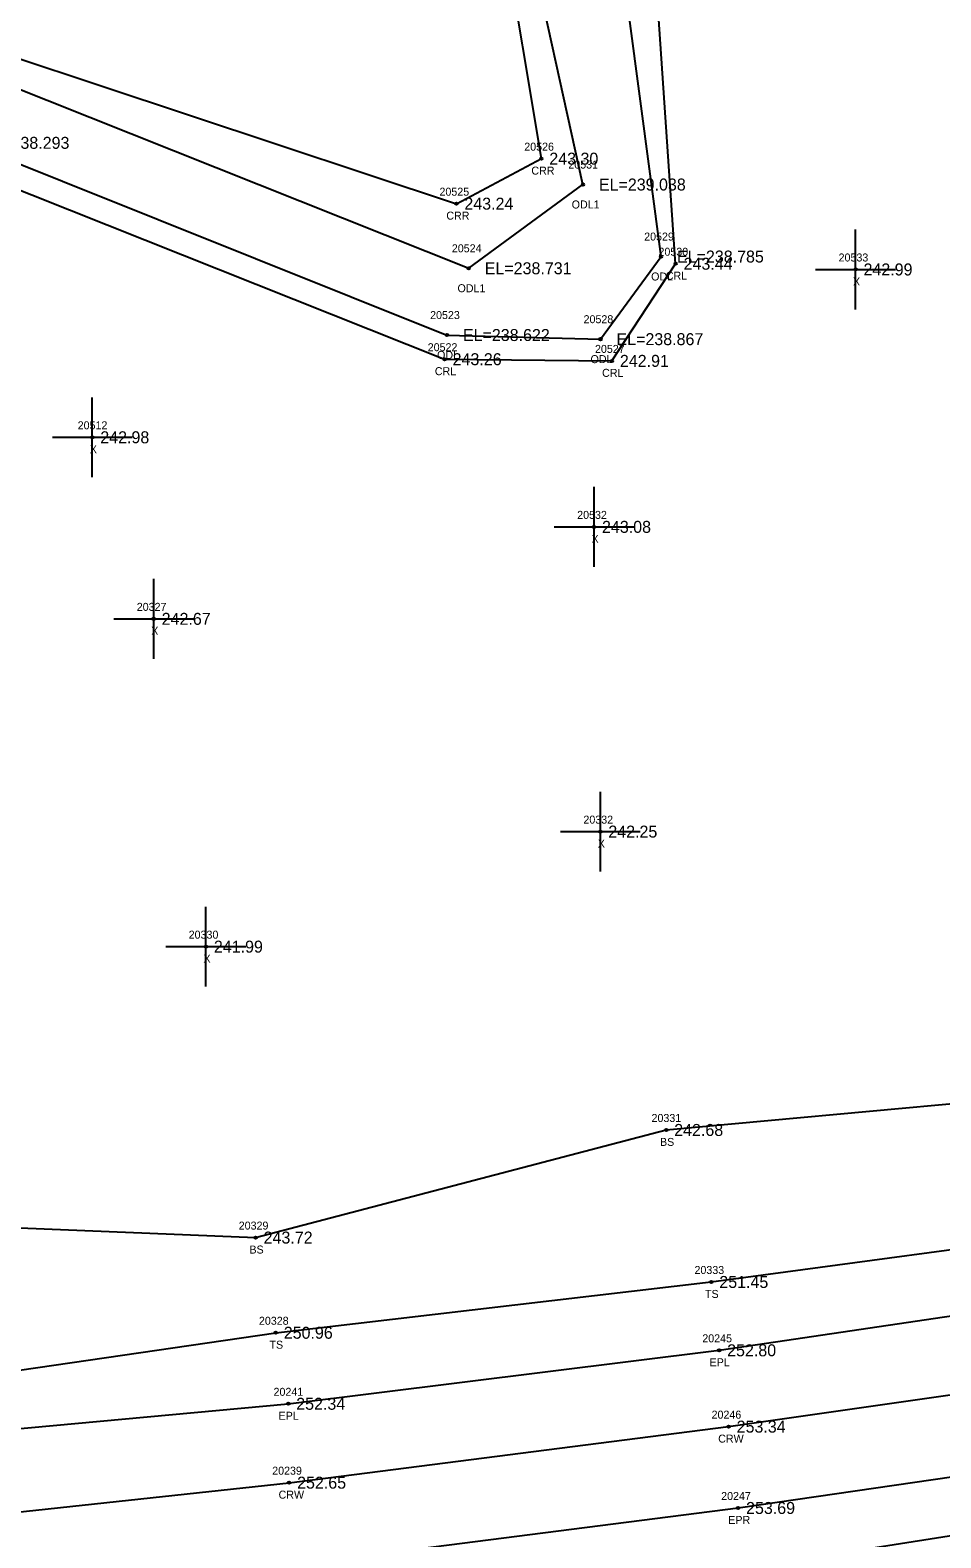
# Model space of a CAD drawing. Extents: x 2275563 to 2277161, y 1075719 to 1076412.
# Drawn here: x 2276399.9 to 2276514, y 1076072.5 to 1076261.3 of the extents above; entities that cross this region are included whole.
import ezdxf

# ---------------------------------------------------------------- set-up
doc = ezdxf.new("R2010")
doc.units = 0
for name, color, linetype in [('RD_DTM_BkLn1', 7, 'Continuous'), ('RD_DTM_BkLn2', 7, 'Continuous'), ('RD_DTM_BkLn_txCode', 7, 'Continuous'), ('RD_EX_H2O', 7, 'Continuous'), ('RD_EX_H2O_txCode', 7, 'Continuous'), ('RD_EX_Misc', 7, 'Continuous'), ('RD_EX_Misc_txCode', 7, 'Continuous'), ('RD_EX_Road', 7, 'Continuous'), ('RD_EX_Road_txCode', 7, 'Continuous'), ('RD_EX_TX_H2O_ELEV', 7, 'Continuous'), ('RD_EX_TX_Misc_ELEV', 7, 'Continuous'), ('RD_EX_TX_Road_ELEV', 7, 'Continuous'), ('RD_HC_Survey_ELEV', 7, 'Continuous'), ('RD_HC_Survey_txCode', 7, 'Continuous'), ('RD_SMD_Locator', 7, 'Continuous')]:
    doc.layers.add(name, color=color, linetype=linetype)

msp = doc.modelspace()

# ---------------------------------------------------------------- linework, layer by layer
at = {"layer": 'RD_DTM_BkLn1'}
msp.add_lwpolyline([(2276380.47, 1076073.8), (2276432.36, 1076079.4), (2276487.41, 1076086.42), (2276535.62, 1076093.32), (2276578.15, 1076099.97), (2276622.03, 1076107.93), (2276668.51, 1076117.27), (2276714.2, 1076127.81), (2276762.94, 1076140.11), (2276806.88, 1076151.96), (2276854.94, 1076166.29), (2276899.73, 1076180.7), (2276952.88, 1076198.57), (2277000.46, 1076214.72), (2277057.1, 1076234.01), (2277134.93, 1076261.07)], dxfattribs=at)
at = {"layer": 'RD_DTM_BkLn2'}
for points in [[(2276352.82, 1076100.61), (2276380.25, 1076112.06), (2276428.17, 1076110.1), (2276479.59, 1076123.58), (2276530.51, 1076128.25), (2276572.26, 1076136.92), (2276616.95, 1076145.31), (2276657.47, 1076152.34)], [(2276378.73, 1076086.44), (2276379.33, 1076090.71), (2276430.69, 1076098.18), (2276485.24, 1076104.54), (2276534.86, 1076111.23), (2276576.67, 1076117.6), (2276619.01, 1076127.99), (2276664.32, 1076137.81), (2276675.37, 1076140.15)], [(2276381.23, 1076060.52), (2276384.72, 1076057.35), (2276432.14, 1076059.24), (2276489.29, 1076068.7), (2276538.36, 1076076.43), (2276580.68, 1076083.56), (2276626.16, 1076090.05), (2276659.02, 1076095.85)]]:
    msp.add_lwpolyline(points, dxfattribs=at)
at = {"layer": 'RD_EX_H2O'}
for points in [[(2276337.52, 1076082.32), (2276338.14, 1076090.91), (2276325.39, 1076121.38), (2276301.23, 1076176.38), (2276301.47, 1076212.03), (2276303.94, 1076212.33), (2276322.96, 1076208.7), (2276333.72, 1076197.42), (2276353.59, 1076194.54), (2276358.22, 1076208.33), (2276360.94, 1076233.4), (2276370.36, 1076250.64), (2276386.18, 1076258.85), (2276454.86, 1076231.51), (2276469.16, 1076242), (2276461.94, 1076274.88), (2276441.6, 1076298.83), (2276443.32, 1076327.87), (2276470.76, 1076362.4), (2276481.62, 1076405.55)], [(2276371.99, 1076084.86), (2276359.12, 1076090.36), (2276349.87, 1076095.47), (2276335.93, 1076128.95), (2276310.08, 1076180.39), (2276310.66, 1076200.13), (2276321.83, 1076198.34), (2276333.62, 1076185.76), (2276354.83, 1076182.14), (2276364.71, 1076198.02), (2276372.09, 1076234.22), (2276380.37, 1076246.34), (2276391.97, 1076247.22), (2276452.13, 1076223.15), (2276471.36, 1076222.63), (2276478.94, 1076232.98), (2276472.33, 1076282.9), (2276448.49, 1076309.21), (2276451.67, 1076322.37), (2276482.4, 1076359.1), (2276495.19, 1076406.32)], [(2276374.66, 1076053.77), (2276377.62, 1076058.48), (2276375.93, 1076085.62), (2276365.46, 1076098.25), (2276358.16, 1076095.88), (2276352.82, 1076100.61), (2276340.06, 1076130.39), (2276314.72, 1076182.94), (2276314.31, 1076195.95), (2276321.34, 1076195.98), (2276333.33, 1076184.02), (2276355.21, 1076176.64), (2276375.26, 1076196.07), (2276380, 1076232.36), (2276383.62, 1076239.24), (2276390.64, 1076244.46), (2276451.84, 1076220.12), (2276472.79, 1076219.91), (2276480.77, 1076232.08), (2276477.11, 1076285.34), (2276453.42, 1076310.35), (2276458.35, 1076317.97), (2276489.24, 1076360.6), (2276498.15, 1076406.79)], [(2276306.58, 1076220.1), (2276325.39, 1076214.04), (2276335.43, 1076205.2), (2276348.24, 1076201.78), (2276353.6, 1076208.85), (2276358.58, 1076232.7), (2276367.82, 1076252.56), (2276386.4, 1076261.78), (2276453.31, 1076239.6), (2276463.95, 1076245.24), (2276459.26, 1076273.53), (2276439.87, 1076297.83), (2276438.91, 1076332.85), (2276467.89, 1076361.53), (2276478.69, 1076404.9)]]:
    msp.add_lwpolyline(points, dxfattribs=at)
at = {"layer": 'RD_EX_Misc'}
for p, q in [((2276503.3, 1076226.36), (2276503.3, 1076236.36)), ((2276498.3, 1076231.36), (2276508.3, 1076231.36)), ((2276407.71, 1076205.34), (2276407.71, 1076215.34)), ((2276402.71, 1076210.34), (2276412.71, 1076210.34)), ((2276470.55, 1076194.12), (2276470.55, 1076204.12)), ((2276465.55, 1076199.12), (2276475.55, 1076199.12)), ((2276415.4, 1076182.6), (2276415.4, 1076192.6)), ((2276410.4, 1076187.6), (2276420.4, 1076187.6)), ((2276471.34, 1076155.95), (2276471.34, 1076165.95)), ((2276466.34, 1076160.95), (2276476.34, 1076160.95)), ((2276421.94, 1076141.54), (2276421.94, 1076151.54)), ((2276416.94, 1076146.54), (2276426.94, 1076146.54))]:
    msp.add_line(p, q, dxfattribs=at)
at = {"layer": 'RD_EX_Road'}
for points in [[(2276379.21, 1076084.39), (2276432.25, 1076089.28), (2276486.22, 1076095.98), (2276535.61, 1076103.32), (2276577.16, 1076110.11), (2276620.86, 1076117.78), (2276666.21, 1076126.9), (2276712, 1076137.22), (2276761.13, 1076149.72), (2276804.56, 1076161.71), (2276851.24, 1076175.53), (2276896.93, 1076190.53), (2276950.19, 1076208.22), (2276997.45, 1076224.3), (2277053.81, 1076243.77), (2277132.14, 1076270.77)], [(2276381.27, 1076063.04), (2276433.15, 1076069.16), (2276488.59, 1076076.23), (2276537.45, 1076083.34), (2276579.64, 1076090.09), (2276624.07, 1076098.24), (2276670.54, 1076107.46), (2276716.67, 1076118.09), (2276765.18, 1076130.28), (2276809.58, 1076142.25), (2276856.93, 1076156.58), (2276903.53, 1076171.63), (2276957.27, 1076189.46), (2277005.85, 1076206.01), (2277060.98, 1076225.07), (2277139.5, 1076252.36)]]:
    msp.add_lwpolyline(points, dxfattribs=at)
at = {"layer": 'RD_SMD_Locator'}
for centre in [(2276463.95, 1076245.24), (2276469.16, 1076242), (2276453.31, 1076239.6), (2276454.86, 1076231.51), (2276478.94, 1076232.98), (2276480.77, 1076232.08), (2276503.3, 1076231.36), (2276452.13, 1076223.15), (2276471.36, 1076222.63), (2276451.84, 1076220.12), (2276472.79, 1076219.91), (2276407.71, 1076210.34), (2276470.55, 1076199.12), (2276415.4, 1076187.6), (2276471.34, 1076160.95), (2276421.94, 1076146.54), (2276479.59, 1076123.58), (2276428.17, 1076110.1), (2276485.24, 1076104.54), (2276430.69, 1076098.18), (2276486.22, 1076095.98), (2276432.25, 1076089.28), (2276487.41, 1076086.42), (2276432.36, 1076079.4), (2276488.59, 1076076.23)]:
    msp.add_circle(centre, 0.15, dxfattribs=at)

# ---------------------------------------------------------------- texts
at = {"layer": 'RD_DTM_BkLn_txCode'}
for s, p in [('20331', (2276477.75, 1076124.58)), ('BS', (2276478.81, 1076121.58)), ('20329', (2276426.05, 1076111.1)), ('BS', (2276427.39, 1076108.1)), ('20333', (2276483.13, 1076105.54)), ('TS', (2276484.45, 1076102.54)), ('20328', (2276428.58, 1076099.18)), ('TS', (2276429.9, 1076096.18))]:
    msp.add_text(s, height=1, dxfattribs=at).set_placement(p)
at = {"layer": 'RD_EX_H2O_txCode'}
for s, p in [('20526', (2276461.81, 1076246.24)), ('20531', (2276467.33, 1076244)), ('CRR', (2276462.7, 1076243.24)), ('20525', (2276451.19, 1076240.6)), ('ODL1', (2276467.75, 1076239)), ('CRR', (2276452.05, 1076237.6)), ('20529', (2276476.83, 1076234.98)), ('20524', (2276452.74, 1076233.51)), ('20530', (2276478.62, 1076233.08)), ('ODL', (2276477.7, 1076229.98)), ('CRL', (2276479.54, 1076230.08)), ('ODL1', (2276453.45, 1076228.51)), ('20523', (2276450.02, 1076225.15)), ('20528', (2276469.24, 1076224.63)), ('20522', (2276449.72, 1076221.12)), ('ODL', (2276450.89, 1076220.15)), ('ODL', (2276470.11, 1076219.63)), ('20527', (2276470.67, 1076220.91)), ('CRL', (2276450.61, 1076218.12)), ('CRL', (2276471.56, 1076217.91))]:
    msp.add_text(s, height=1, dxfattribs=at).set_placement(p)
at = {"layer": 'RD_EX_Misc_txCode'}
for s, p in [('20533', (2276501.18, 1076232.36)), ('X', (2276502.98, 1076229.36)), ('20512', (2276405.88, 1076211.34)), ('X', (2276407.4, 1076208.34)), ('20532', (2276468.44, 1076200.12)), ('X', (2276470.24, 1076197.12)), ('20327', (2276413.28, 1076188.6)), ('X', (2276415.09, 1076185.6)), ('20332', (2276469.22, 1076161.95)), ('X', (2276471.02, 1076158.95)), ('20330', (2276419.78, 1076147.54)), ('X', (2276421.63, 1076144.54))]:
    msp.add_text(s, height=1, dxfattribs=at).set_placement(p)
at = {"layer": 'RD_EX_Road_txCode'}
for s, p in [('20245', (2276484.11, 1076096.98)), ('EPL', (2276485.02, 1076093.98)), ('20241', (2276430.41, 1076090.28)), ('EPL', (2276431.04, 1076087.28)), ('20247', (2276486.47, 1076077.23)), ('EPR', (2276487.36, 1076074.23))]:
    msp.add_text(s, height=1, dxfattribs=at).set_placement(p)
at = {"layer": 'RD_EX_TX_H2O_ELEV'}
for s, p in [('EL=238.293', (2276393.97, 1076246.47)), ('243.30', (2276464.95, 1076244.49)), ('EL=239.038', (2276471.16, 1076241.25)), ('243.24', (2276454.31, 1076238.85)), ('EL=238.785', (2276480.94, 1076232.23)), ('EL=238.731', (2276456.86, 1076230.76)), ('243.44', (2276481.77, 1076231.33)), ('EL=238.622', (2276454.13, 1076222.4)), ('EL=238.867', (2276473.36, 1076221.88)), ('243.26', (2276452.84, 1076219.37)), ('242.91', (2276473.79, 1076219.16))]:
    msp.add_text(s, height=1.5, dxfattribs=at).set_placement(p)
at = {"layer": 'RD_EX_TX_Misc_ELEV'}
for s, p in [('242.99', (2276504.3, 1076230.61)), ('242.98', (2276408.71, 1076209.59)), ('243.08', (2276471.55, 1076198.37)), ('242.67', (2276416.4, 1076186.85)), ('242.25', (2276472.34, 1076160.2)), ('241.99', (2276422.94, 1076145.79)), ('242.68', (2276480.59, 1076122.83)), ('243.72', (2276429.17, 1076109.35)), ('251.45', (2276486.24, 1076103.79)), ('250.96', (2276431.69, 1076097.43))]:
    msp.add_text(s, height=1.5, dxfattribs=at).set_placement(p)
at = {"layer": 'RD_EX_TX_Road_ELEV'}
for s, p in [('252.80', (2276487.22, 1076095.23)), ('252.34', (2276433.25, 1076088.53)), ('253.69', (2276489.59, 1076075.48))]:
    msp.add_text(s, height=1.5, dxfattribs=at).set_placement(p)
at = {"layer": 'RD_HC_Survey_ELEV'}
for s, p in [('253.34', (2276488.41, 1076085.67)), ('252.65', (2276433.36, 1076078.65))]:
    msp.add_text(s, height=1.5, dxfattribs=at).set_placement(p)
at = {"layer": 'RD_HC_Survey_txCode'}
for s, p in [('20246', (2276485.27, 1076087.42)), ('CRW', (2276486.1, 1076084.42)), ('20239', (2276430.24, 1076080.4)), ('CRW', (2276431.04, 1076077.4))]:
    msp.add_text(s, height=1, dxfattribs=at).set_placement(p)

doc.saveas('drawing.dxf')
